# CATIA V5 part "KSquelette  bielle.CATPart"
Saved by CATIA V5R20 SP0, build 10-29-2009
Part number: K_Squelette  bielle
Bounding box of the stored display mesh (mm): x -50 to 50, y -69.737 to 59.179, z 319.317 to 643.362
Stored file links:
  C:\Users\thinkmotion1\Desktop\Khaled_IAO_Pack2\IAO_2010_1392_rragonneau\CATIA_1392_rragonneau\KSquelette  bielle.CATPart
  D:\Documents\Scolaire\MM2\IAO\Squelette\Product1.CATProduct
  C:\Users\thinkmotion1\Desktop\Khaled_IAO_Pack2\IAO_2010_1392_rragonneau\CATIA_1392_rragonneau\KSquelette vilebrequin.CATPart
  C:\Users\thinkmotion1\Desktop\Khaled_IAO_Pack2\IAO_2010_1392_rragonneau\CATIA_1392_rragonneau\KSquelette de base.CATPart
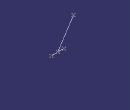
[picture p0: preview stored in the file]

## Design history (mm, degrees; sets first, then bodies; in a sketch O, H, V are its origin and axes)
Set1
  Line1: type PtPt, FirstPoint DatumPoint1, SecondPoint DatumPoint2
  Line2: type PtPt, FirstPoint DatumPoint3, SecondPoint Point1
Set2
  DatumPoint1 to DatumPoint3: linked copy from another document
  Point1: linked copy from another document
Body1 (main body)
